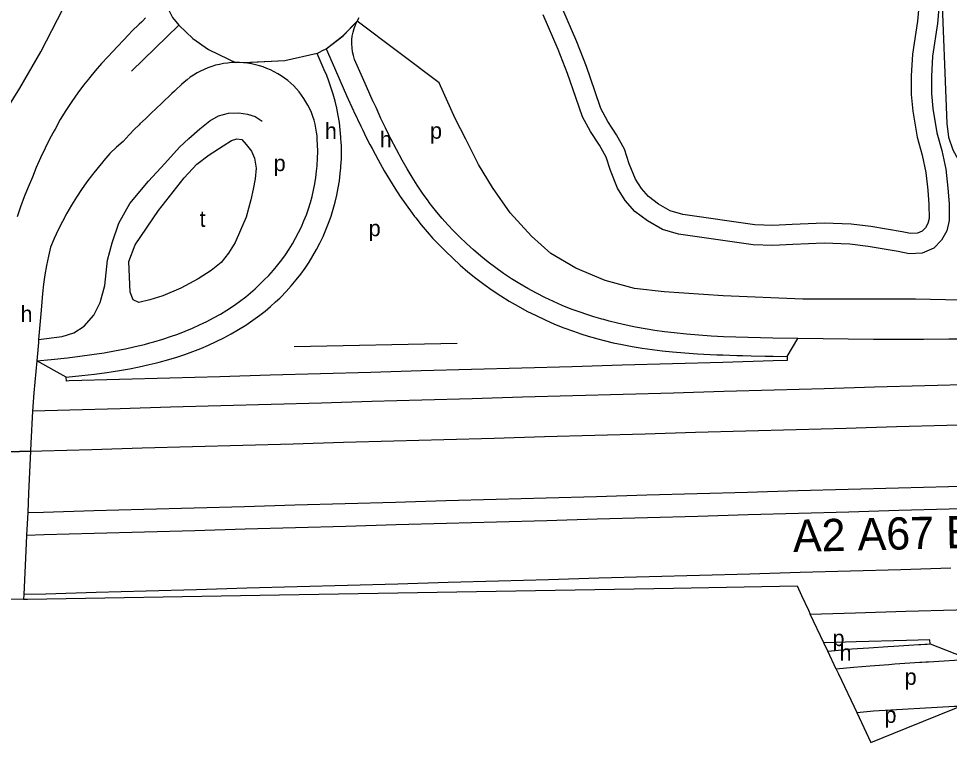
# Model space of a CAD drawing. Extents: x 158358 to 160383, y 379531 to 380764.
# Drawn here: x 159279.5 to 159510.8, y 379530.7 to 379710.4 of the extents above; entities that cross this region are included whole.
import ezdxf

# ---------------------------------------------------------------- set-up
doc = ezdxf.new("R2010")
doc.units = 0
for name, color, linetype in [('BLT_Basislijn', 7, 'Continuous'), ('BLT_Centroide', 7, 'Continuous'), ('BLT_Gemeentegrens', 7, 'Continuous'), ('BLT_Straatnaam_hoofdweg', 7, 'Continuous'), ('BLT_Vlakafsluiter', 7, 'Continuous')]:
    doc.layers.add(name, color=color, linetype=linetype)

msp = doc.modelspace()

# ---------------------------------------------------------------- linework, layer by layer
at = {"layer": 'BLT_Basislijn'}
msp.add_line((159347.94, 379629.02), (159388.44, 379629.78), dxfattribs=at)
for points in [[(159271.86, 379679.96), (159273.32, 379682.86), (159279.82, 379693.13), (159285.05, 379702.13), (159291.93, 379715.56), (159296.39, 379728.28), (159296.31, 379745.8)], [(159508.74, 379720.04), (159510.15, 379684.35), (159510.58, 379680.95), (159511.63, 379677.83), (159512.96, 379675.4), (159515.12, 379672.76), (159517.23, 379670.91), (159520.09, 379669.22), (159523.31, 379668.22), (159525, 379667.9), (159526.69, 379667.74), (160139.53, 379691.14), (160142.9, 379691.52), (160144.79, 379692.1), (160146.54, 379692.75), (160148.23, 379693.53), (160149.78, 379694.5), (160152.48, 379696.8), (160183.67, 379730.79)], [(159508.74, 379720.04), (159507.82, 379709.13), (159506.58, 379701.04), (159506.28, 379696), (159506.28, 379691.77), (159506.62, 379688.08), (159507.67, 379682.04), (159508.86, 379677.66), (159509.84, 379673), (159510.41, 379668.28), (159510.69, 379664.39), (159510.71, 379660.29), (159510.16, 379657.69), (159508.8, 379655.39), (159506.87, 379653.4), (159503.98, 379652.17), (159500.76, 379652.01), (159498.07, 379652.57), (159490.54, 379653.83), (159485.99, 379654.39), (159479.64, 379654.63), (159471.89, 379654.28), (159466.93, 379654.05), (159461.98, 379654.22), (159443.45, 379656.85), (159439.45, 379658.06), (159435.73, 379660.15), (159432.62, 379662.48), (159430.2, 379665.19), (159428.32, 379668.26), (159426.54, 379672.65), (159425.46, 379675.99), (159423.8, 379678.98), (159421.62, 379682.33), (159419.62, 379686.01), (159417.92, 379690.77), (159415.87, 379696.77), (159413.56, 379702.72), (159409.87, 379711.35)], [(159503.32, 379715.27), (159502.85, 379709.72), (159501.6, 379701.56), (159501.28, 379696.15), (159501.28, 379691.54), (159501.66, 379687.43), (159502.78, 379680.95), (159504, 379676.49), (159504.9, 379672.18), (159505.44, 379667.8), (159505.69, 379664.2), (159505.71, 379660.8), (159505.44, 379659.54), (159504.79, 379658.44), (159503.98, 379657.6), (159502.84, 379657.12), (159501.14, 379657.03), (159499, 379657.48), (159491.26, 379658.78), (159486.39, 379659.37), (159479.62, 379659.63), (159471.66, 379659.27), (159466.91, 379659.05), (159462.42, 379659.21), (159444.53, 379661.75), (159441.42, 379662.69), (159438.47, 379664.35), (159436.01, 379666.19), (159434.23, 379668.19), (159432.8, 379670.51), (159431.24, 379674.36), (159430.06, 379678), (159428.08, 379681.56), (159425.92, 379684.88), (159424.2, 379688.06), (159422.64, 379692.42), (159420.57, 379698.48), (159418.19, 379704.6), (159414.49, 379713.26)], [(159363.61, 379709.77), (159364.1, 379710.62)], [(159311.04, 379710.57), (159310.36, 379709.84), (159310.04, 379709.53), (159309.46, 379708.99), (159307.64, 379707.27), (159306.89, 379706.47), (159302.84, 379702.16), (159301.69, 379700.93), (159300.1, 379699.21), (159298.57, 379697.46), (159297.08, 379695.67), (159296.84, 379695.38), (159295.64, 379693.85), (159294.25, 379691.99), (159292.7, 379689.8), (159291.22, 379687.58), (159289.81, 379685.31), (159288.56, 379682.96), (159288.32, 379682.54), (159287.29, 379680.62), (159286.09, 379678.26), (159284.96, 379675.86), (159283.91, 379673.44), (159282.93, 379670.99), (159281.88, 379668.57), (159280.91, 379666.13), (159280.01, 379663.65), (159279.18, 379661.15)], [(159319.29, 379708.77), (159313.42, 379703.05), (159307.58, 379697.36)], [(159473.13, 379630.96), (159466.88, 379631.08), (159460.8, 379631.23), (159454.62, 379631.39), (159454.61, 379631.39), (159453.14, 379631.47), (159451.54, 379631.57), (159448.47, 379631.78), (159445.42, 379632.04), (159442.38, 379632.35), (159439.97, 379632.65), (159437.57, 379632.98), (159435.18, 379633.36), (159432.81, 379633.79), (159430.46, 379634.27), (159428.34, 379634.75), (159426.24, 379635.29), (159424.9, 379635.66), (159424.44, 379635.78), (159424.15, 379635.86), (159422.42, 379636.36), (159420.71, 379636.9), (159419.01, 379637.48), (159416.78, 379638.29), (159414.58, 379639.18), (159412.4, 379640.13), (159410.25, 379641.14), (159408.14, 379642.21), (159406.05, 379643.35), (159404, 379644.55), (159401.99, 379645.8), (159400.02, 379647.12), (159398.08, 379648.49), (159396.19, 379649.92), (159394.33, 379651.41), (159392.53, 379652.95), (159390.76, 379654.54), (159389.05, 379656.18), (159387.58, 379657.67), (159386.15, 379659.19), (159384.76, 379660.76), (159383.41, 379662.36), (159382.1, 379663.99), (159381.82, 379664.35), (159381.53, 379664.73), (159381.25, 379665.11), (159379.87, 379667.05), (159378.55, 379669.04), (159377.26, 379671.06), (159376.03, 379673.12), (159374.83, 379675.21), (159373.38, 379677.86), (159371.99, 379680.55), (159371.48, 379681.57), (159370.65, 379683.28), (159369.54, 379685.62), (159369.34, 379686.04), (159368.33, 379688.28), (159367.7, 379689.62), (159367.63, 379689.76), (159365.93, 379693.51), (159364.25, 379697.29), (159363.3, 379699.47), (159362.98, 379700.26), (159362.69, 379701.2), (159362.48, 379702.15), (159362.34, 379703.12), (159362.29, 379704.1), (159362.31, 379705.08), (159362.42, 379706.06), (159362.6, 379707.02), (159362.86, 379707.96), (159363.2, 379708.88), (159363.55, 379709.63)], [(159363.55, 379709.63), (159363.61, 379709.77)], [(159291.36, 379621.41), (159295.21, 379621.77), (159298.33, 379622.13), (159301.44, 379622.54), (159304.55, 379623.02), (159307.02, 379623.46), (159309.49, 379623.95), (159311.95, 379624.5), (159313.41, 379624.85), (159314.39, 379625.1), (159316.82, 379625.77), (159318.83, 379626.38), (159320.82, 379627.04), (159322.8, 379627.75), (159324.76, 379628.52), (159326.7, 379629.33), (159328.61, 379630.21), (159330.5, 379631.14), (159332.35, 379632.14), (159334.18, 379633.19), (159335.96, 379634.31), (159337.71, 379635.49), (159339.41, 379636.73), (159340.77, 379637.79), (159342.09, 379638.89), (159343.37, 379640.04), (159344.41, 379641.02), (159344.62, 379641.23), (159345.97, 379642.61), (159347.26, 379644.04), (159348.5, 379645.52), (159349.61, 379646.95), (159350.67, 379648.42), (159351.67, 379649.92), (159352.63, 379651.46), (159353.52, 379653.04), (159354.36, 379654.64), (159355.14, 379656.27), (159355.86, 379657.94), (159356.53, 379659.62), (159357.13, 379661.33), (159357.67, 379663.06), (159358.15, 379664.8), (159358.56, 379666.56), (159358.92, 379668.34), (159359.21, 379670.13), (159359.43, 379671.92), (159359.56, 379673.37), (159359.59, 379673.73), (159359.69, 379675.54), (159359.72, 379677.35), (159359.72, 379677.58), (159359.69, 379679.16), (159359.68, 379679.29), (159359.59, 379680.96), (159359.43, 379682.77), (159359.2, 379684.56), (159358.91, 379686.35), (159358.56, 379688.13), (159358.14, 379689.89), (159357.66, 379691.63), (159357.12, 379693.36), (159356.61, 379694.82), (159356.05, 379696.27), (159355.45, 379697.69), (159353.69, 379701.7)], [(159353.67, 379701.74), (159355.01, 379702.44), (159355.9, 379702.9)], [(159353.69, 379701.7), (159353.67, 379701.74)], [(159355.9, 379702.9), (159355.92, 379702.85)], [(159355.92, 379702.85), (159357.96, 379698.2), (159359.31, 379695.11), (159361, 379691.3), (159362.73, 379687.5), (159362.8, 379687.35), (159364.51, 379683.72), (159365.01, 379682.71), (159365.89, 379680.9), (159366.78, 379679.16), (159367.32, 379678.11), (159368.8, 379675.34), (159370.34, 379672.61), (159371.62, 379670.44), (159372.95, 379668.31), (159374.33, 379666.2), (159375.76, 379664.13), (159377.25, 379662.1), (159377.86, 379661.3), (159378.16, 379660.91), (159379.55, 379659.18), (159380.98, 379657.48), (159382.46, 379655.82), (159383.98, 379654.2), (159385.54, 379652.62), (159387.36, 379650.88), (159389.23, 379649.19), (159391.15, 379647.55), (159393.12, 379645.98), (159395.13, 379644.46), (159397.18, 379643), (159399.28, 379641.6), (159401.42, 379640.27), (159403.6, 379639), (159405.81, 379637.79), (159408.06, 379636.65), (159410.34, 379635.57), (159412.65, 379634.57), (159414.99, 379633.63), (159417.35, 379632.76), (159419.16, 379632.15), (159420.98, 379631.57), (159422.81, 379631.04), (159423.12, 379630.96), (159425.03, 379630.46), (159427.26, 379629.93), (159429.5, 379629.46), (159431.97, 379629), (159434.46, 379628.59), (159436.94, 379628.24), (159439.44, 379627.93), (159441.94, 379627.67), (159445.06, 379627.41), (159448.19, 379627.19), (159451.32, 379627.02), (159452.95, 379626.95), (159454.45, 379626.89), (159457.97, 379626.78), (159459.36, 379626.74), (159461.48, 379626.69), (159464.99, 379626.61), (159465.31, 379626.6), (159466.96, 379626.57), (159470.43, 379626.49)], [(159284.05, 379625.46), (159287.58, 379625.78), (159291.66, 379626.2), (159294.71, 379626.56), (159297.73, 379626.97), (159300.74, 379627.44), (159303.72, 379627.96), (159306.09, 379628.43), (159308.44, 379628.95), (159310.77, 379629.52), (159312.15, 379629.89), (159313.07, 379630.14), (159315.35, 379630.82), (159317.22, 379631.44), (159319.08, 379632.09), (159320.91, 379632.8), (159322.72, 379633.55), (159324.49, 379634.34), (159326.24, 379635.19), (159327.95, 379636.08), (159329.63, 379637.03), (159331.27, 379638.03), (159332.87, 379639.08), (159334.42, 379640.18), (159335.93, 379641.33), (159337.12, 379642.3), (159338.27, 379643.31), (159339.39, 379644.36), (159340.29, 379645.25), (159340.47, 379645.43), (159341.67, 379646.65), (159342.81, 379647.91), (159343.9, 379649.22), (159344.89, 379650.48), (159345.82, 379651.78), (159346.71, 379653.11), (159347.55, 379654.47), (159348.34, 379655.86), (159349.08, 379657.28), (159349.77, 379658.72), (159350.41, 379660.19), (159351, 379661.68), (159351.53, 379663.19), (159352.01, 379664.72), (159352.43, 379666.26), (159352.8, 379667.82), (159353.11, 379669.39), (159353.37, 379670.97), (159353.56, 379672.55), (159353.68, 379673.83), (159353.71, 379674.15), (159353.78, 379675.5), (159353.79, 379675.74), (159353.82, 379677.34), (159353.82, 379677.55), (159353.79, 379678.94), (159353.7, 379680.54), (159353.65, 379681.25), (159353.54, 379682.23), (159353.38, 379683.21), (159353.17, 379684.19), (159352.91, 379685.16), (159352.6, 379686.11), (159352.25, 379687.04), (159351.85, 379687.96), (159351.4, 379688.86), (159350.91, 379689.73), (159350.38, 379690.57), (159349.8, 379691.39), (159349.19, 379692.18), (159348.54, 379692.94), (159347.85, 379693.66), (159347.12, 379694.35), (159346.36, 379695), (159345.57, 379695.61), (159344.75, 379696.18), (159343.9, 379696.71), (159343.03, 379697.2), (159342.13, 379697.64), (159341.21, 379698.04), (159340.28, 379698.39), (159339.33, 379698.7), (159338.36, 379698.95), (159337.38, 379699.16), (159336.39, 379699.32), (159335.72, 379699.39)], [(159333.4, 379699.5), (159332.4, 379699.45), (159331.41, 379699.36), (159330.42, 379699.22), (159329.44, 379699.03), (159328.46, 379698.79), (159327.51, 379698.51), (159326.56, 379698.17), (159325.64, 379697.79), (159324.74, 379697.36), (159323.85, 379696.89), (159323, 379696.38), (159322.17, 379695.82), (159321.37, 379695.22), (159320.6, 379694.59), (159320, 379694.05), (159318.61, 379692.73), (159318.26, 379692.41), (159317.58, 379691.76), (159314.97, 379689.3), (159313.74, 379688.14), (159312.39, 379686.83), (159311.03, 379685.53), (159309.65, 379684.23), (159309.43, 379684.02), (159308.3, 379682.9), (159306.99, 379681.53), (159305.51, 379679.9), (159303.81, 379678.43), (159302.14, 379676.89), (159300.72, 379675.17), (159300.45, 379674.86), (159299.25, 379673.44), (159297.84, 379671.67), (159296.47, 379669.85), (159295.15, 379667.98), (159293.88, 379666.06), (159292.67, 379664.1), (159291.51, 379662.09), (159290.41, 379660.04), (159289.36, 379657.95), (159288.37, 379655.82), (159287.45, 379653.65), (159286.91, 379651.38), (159286.44, 379649.08), (159286.04, 379646.78), (159285.7, 379644.47), (159285.44, 379642.14), (159285.26, 379640.08), (159285.14, 379638.02), (159284.48, 379630.75)], [(159335.4, 379699.43), (159334.4, 379699.49), (159333.4, 379699.5)], [(159335.72, 379699.39), (159335.4, 379699.43)], [(159528.55, 379640.14), (159502.38, 379640.72), (159474.36, 379640.72), (159454.58, 379641.55), (159439.91, 379642.53), (159432.49, 379643.36), (159425.24, 379645.34), (159417.99, 379648.47), (159411.72, 379652.1), (159406.94, 379656.38), (159401.67, 379662.16), (159397.22, 379668.42), (159393.76, 379674.19), (159390.62, 379680.46), (159387.99, 379685.57), (159384.03, 379694.47)], [(159284.48, 379630.75), (159290.34, 379631.49), (159293.19, 379632.4), (159295.78, 379634.07), (159298.2, 379636.76), (159299.76, 379639.88), (159300.89, 379644.14), (159301.59, 379650.44), (159302.76, 379654.76), (159304.43, 379659.6), (159307.17, 379664.5), (159311.8, 379670.05), (159315.85, 379674.44), (159319.51, 379678.47), (159321.83, 379680.63), (159324.57, 379683), (159327, 379684.99), (159329.2, 379686.28), (159331.62, 379686.87), (159334.26, 379686.98), (159336.36, 379686.66), (159338.28, 379686.12), (159340.06, 379684.93)], [(159284.48, 379630.75), (159284.41, 379629.97), (159284, 379625.46)], [(159516.86, 379630.82), (159510.61, 379630.77), (159504.36, 379630.73), (159498.12, 379630.73), (159491.87, 379630.75), (159485.62, 379630.79), (159479.38, 379630.86), (159473.13, 379630.96)], [(159284, 379625.46), (159283.28, 379617.51), (159282.94, 379612.92)], [(159284, 379625.46), (159284.05, 379625.46)], [(159470.43, 379626.49), (159470.46, 379625.49), (159466.98, 379625.39), (159454.48, 379625.04), (159441.99, 379624.68), (159429.49, 379624.33), (159417, 379623.97), (159404.5, 379623.62), (159392.01, 379623.26), (159379.51, 379622.91), (159367.02, 379622.56), (159354.53, 379622.2), (159342.03, 379621.85), (159329.54, 379621.49), (159317.04, 379621.14), (159304.55, 379620.78), (159292.05, 379620.43), (159291.39, 379620.41), (159291.36, 379621.41)], [(159517.17, 379619.57), (159504.67, 379619.21), (159492.18, 379618.86), (159479.68, 379618.5), (159467.19, 379618.15), (159454.69, 379617.79), (159442.2, 379617.44), (159429.7, 379617.08), (159417.21, 379616.73), (159404.71, 379616.37), (159392.22, 379616.02), (159379.72, 379615.66), (159367.23, 379615.31), (159354.73, 379614.95), (159342.24, 379614.6), (159329.74, 379614.24), (159317.25, 379613.89), (159304.75, 379613.53), (159292.26, 379613.18), (159282.99, 379612.92)], [(159282.94, 379612.92), (159282.58, 379605.03), (159282.49, 379603.05)], [(159282.99, 379612.92), (159282.94, 379612.92)], [(159282.48, 379603), (159285.24, 379603.08), (159297.73, 379603.43), (159310.22, 379603.79), (159322.72, 379604.14), (159335.21, 379604.5), (159347.71, 379604.85), (159360.2, 379605.2), (159372.7, 379605.56), (159385.19, 379605.91), (159397.69, 379606.27), (159410.18, 379606.62), (159422.68, 379606.98), (159435.17, 379607.33), (159447.67, 379607.69), (159460.16, 379608.04), (159472.66, 379608.4), (159485.15, 379608.75), (159497.65, 379609.11), (159510.14, 379609.46), (159522.64, 379609.82)], [(159282.48, 379603), (159281.99, 379592.54), (159281.77, 379587.77)], [(159282.49, 379603.05), (159282.48, 379603)], [(159281.77, 379587.77), (159285.67, 379587.88), (159298.16, 379588.24), (159310.66, 379588.59), (159323.15, 379588.95), (159335.65, 379589.3), (159348.14, 379589.66), (159360.64, 379590.01), (159373.13, 379590.37), (159385.63, 379590.72), (159398.12, 379591.08), (159410.62, 379591.43), (159423.11, 379591.78), (159435.61, 379592.14), (159448.1, 379592.49), (159460.6, 379592.85), (159473.09, 379593.2), (159485.59, 379593.56), (159498.08, 379593.91), (159510.58, 379594.27), (159523.07, 379594.62)], [(159281.5, 379582.16), (159285.83, 379582.28), (159298.32, 379582.64), (159310.82, 379582.99), (159323.31, 379583.35), (159335.81, 379583.7), (159348.3, 379584.06), (159360.8, 379584.41), (159373.29, 379584.77), (159385.79, 379585.12), (159398.28, 379585.48), (159410.78, 379585.83), (159423.27, 379586.19), (159435.76, 379586.54), (159448.26, 379586.9), (159460.75, 379587.25), (159473.25, 379587.61), (159485.74, 379587.96), (159498.24, 379588.32), (159510.73, 379588.67), (159523.23, 379589.03)], [(159281.77, 379587.77), (159281.5, 379582.16)], [(159281.5, 379582.16), (159281.4, 379580.05), (159280.8, 379567.39)], [(159511.15, 379573.93), (159498.66, 379573.57), (159486.16, 379573.22), (159473.67, 379572.86), (159461.17, 379572.51), (159448.68, 379572.15), (159436.18, 379571.8), (159423.69, 379571.44), (159411.19, 379571.09), (159398.7, 379570.73), (159386.2, 379570.38), (159373.71, 379570.02), (159361.21, 379569.67), (159348.72, 379569.31), (159336.22, 379568.96), (159323.73, 379568.6), (159311.23, 379568.25), (159298.74, 379567.9), (159286.24, 379567.54), (159280.8, 379567.39)], [(159280.8, 379567.39), (159280.75, 379566.26)], [(159476.2, 379562.58), (159487.42, 379562.9), (159499.91, 379563.25), (159512.41, 379563.61), (159524.9, 379563.96), (159537.4, 379564.32), (159549.89, 379564.67), (159562.39, 379565.03), (159573.07, 379565.33)], [(159505.95, 379555.17), (159505.93, 379556.17), (159500.12, 379556.01), (159487.62, 379555.65), (159479.57, 379555.42)], [(159480.55, 379553.36), (159482.39, 379553.54), (159486.55, 379553.9), (159490.71, 379554.22), (159495.46, 379554.54), (159496.95, 379554.63), (159503.19, 379555.01), (159503.69, 379555.04), (159504.63, 379555.09), (159505.28, 379555.13), (159505.95, 379555.17)], [(159515.93, 379551.25), (159505.55, 379550.64), (159504.9, 379550.6), (159503.95, 379550.55), (159503.45, 379550.51), (159497.23, 379550.11), (159495.75, 379550), (159491.04, 379549.66), (159486.92, 379549.32), (159482.65, 379548.92)], [(159487.76, 379538.14), (159491.91, 379538.52), (159512.02, 379539.67), (159513.59, 379539.72)]]:
    msp.add_lwpolyline(points, dxfattribs=at)
msp.add_lwpolyline([(159309.35, 379639.87), (159307.95, 379640.57), (159307.2, 379642.51), (159306.87, 379650.05), (159308.49, 379654.25), (159314.3, 379662.75), (159320.6, 379670.82), (159323.77, 379674.26), (159326.89, 379676.58), (159330.34, 379678.84), (159332.44, 379680.13), (159333.73, 379680.56), (159334.97, 379680.34), (159336.04, 379679.16), (159337.39, 379677.49), (159338.14, 379675.71), (159338.52, 379673.29), (159338.31, 379670.65), (159337.77, 379668.02), (159337.18, 379665.38), (159336.04, 379661.12), (159334.65, 379657.84), (159333.3, 379654.82), (159331.63, 379652.13), (159329.86, 379649.87), (159327.38, 379647.83), (159324.1, 379645.78), (159319.84, 379643.46), (159315.38, 379641.53), (159312.09, 379640.56)], close=True, dxfattribs=at)
at = {"layer": 'BLT_Gemeentegrens'}
msp.add_line((159479.57, 379555.42), (159476.2, 379562.58), dxfattribs=at)
for points in [[(159280.75, 379566.26), (159281.75, 379566.28), (159339.48, 379567.26), (159442.2, 379569.01), (159472.92, 379569.54), (159474.04, 379567.16), (159475.74, 379563.55), (159476.2, 379562.58)], [(159280.75, 379566.26), (159271.73, 379566.11)], [(159480.55, 379553.36), (159479.57, 379555.42)], [(159482.65, 379548.92), (159480.55, 379553.36)], [(159482.65, 379548.92), (159483.23, 379547.71), (159487.76, 379538.14)], [(159487.76, 379538.14), (159491.22, 379530.71), (159500, 379534.2), (159512.52, 379539.29), (159513.59, 379539.72)]]:
    msp.add_lwpolyline(points, dxfattribs=at)
at = {"layer": 'BLT_Vlakafsluiter'}
for p, q in [((159360.1, 379706.12), (159363.61, 379709.77)), ((159360.14, 379706.08), (159363.55, 379709.63)), ((159384.03, 379694.47), (159363.61, 379709.77)), ((159355.9, 379702.9), (159360.1, 379706.12)), ((159355.92, 379702.85), (159360.14, 379706.08)), ((159353.67, 379701.74), (159345.65, 379699.92)), ((159353.69, 379701.7), (159345.66, 379699.87)), ((159345.65, 379699.92), (159335.4, 379699.43)), ((159345.66, 379699.87), (159335.72, 379699.39)), ((159470.43, 379626.49), (159473.13, 379630.96)), ((159291.36, 379621.41), (159284.05, 379625.46)), ((159273.46, 379602.79), (159282.49, 379603.05)), ((159273.46, 379602.74), (159282.48, 379603)), ((159505.95, 379555.17), (159515.93, 379551.25))]:
    msp.add_line(p, q, dxfattribs=at)
for points in [[(159314.66, 379722.04), (159315.09, 379720.15), (159315.45, 379716.84), (159316.25, 379713.61), (159317.71, 379710.62), (159319.29, 379708.77)], [(159319.29, 379708.77), (159322.78, 379705.47), (159326.71, 379702.7), (159331.66, 379700.34), (159333.4, 379699.5)], [(159284.05, 379625.46), (159283.33, 379617.5), (159282.99, 379612.92)]]:
    msp.add_lwpolyline(points, dxfattribs=at)

# ---------------------------------------------------------------- texts
at = {"layer": 'BLT_Centroide'}
for s, p in [('h', (159355.59, 379680.52)), ('p', (159381.73, 379680.57)), ('h', (159369.25, 379678.39)), ('p', (159342.88, 379672.52)), ('t', (159324.47, 379658.69)), ('p', (159366.49, 379656.36)), ('h', (159279.98, 379635.06)), ('p', (159481.73, 379554.62)), ('h', (159483.47, 379550.97)), ('p', (159499.66, 379545)), ('p', (159494.64, 379535.55))]:
    msp.add_text(s, height=4, dxfattribs=at).set_placement(p)
at = {"layer": 'BLT_Straatnaam_hoofdweg'}
msp.add_text('A2 A67 E25 E34', height=8, rotation=1.3536, dxfattribs=at).set_placement((159471.96, 379577.96))

doc.saveas('drawing.dxf')
